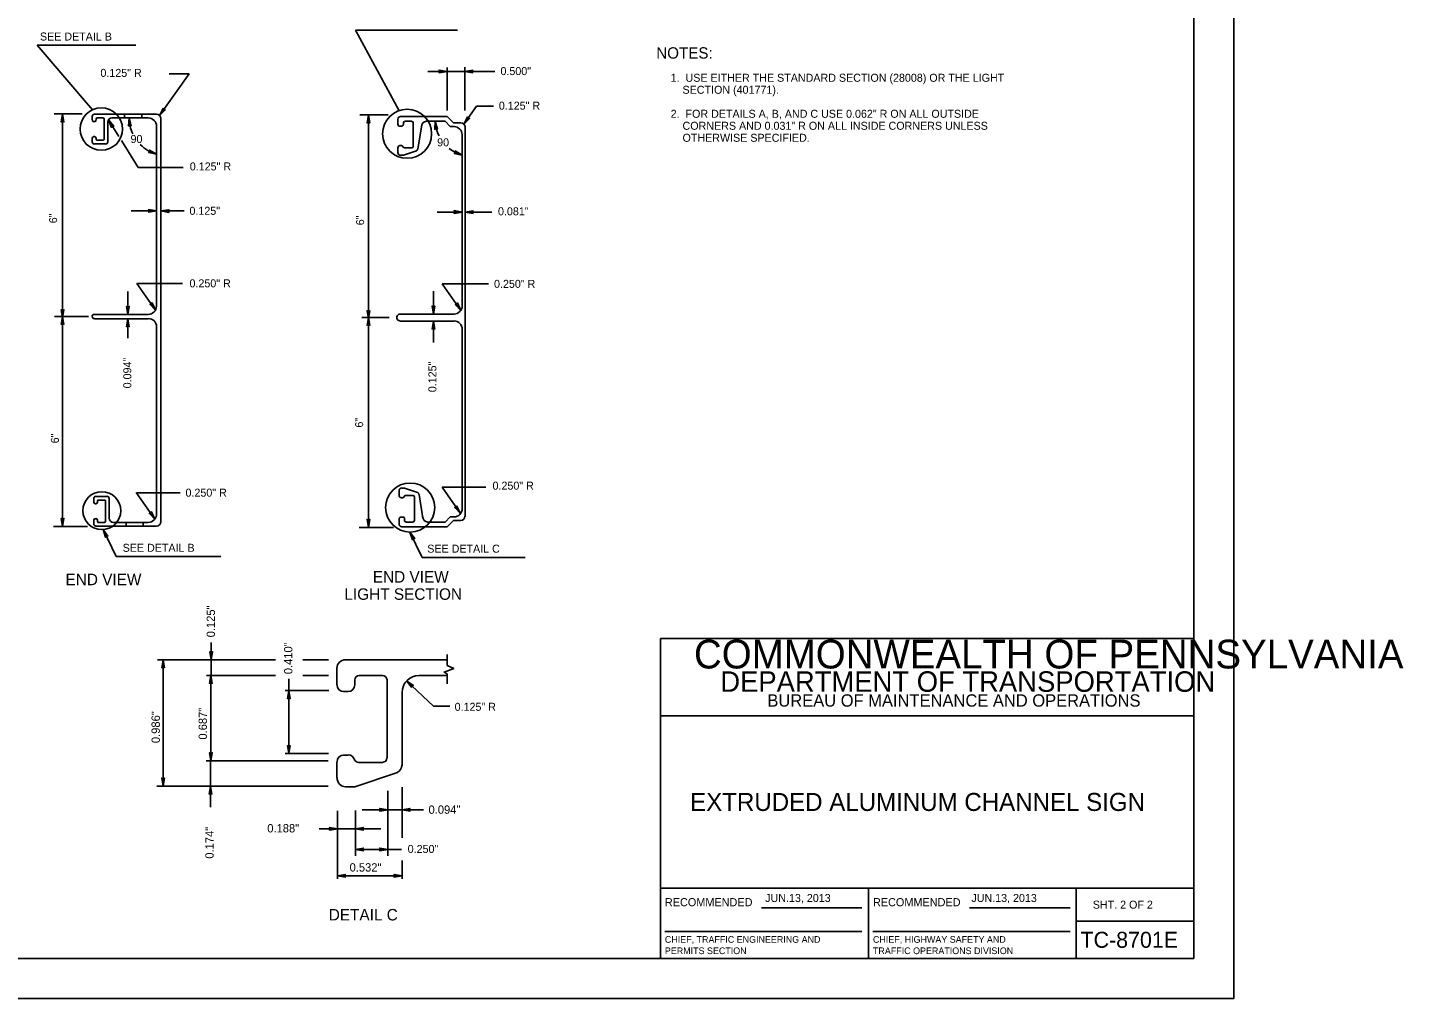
# Model space of a CAD drawing. Extents: x 647822 to 649292, y 298458 to 299646.
# Drawn here: x 648211 to 648727, y 298458 to 298822 of the extents above; entities that cross this region are included whole.
import ezdxf

# ---------------------------------------------------------------- set-up
doc = ezdxf.new("R2010")
doc.units = 0
for name, color, linetype in [('1', 7, 'Continuous'), ('2', 7, 'Continuous'), ('3', 7, 'Continuous'), ('XCS-GRID-MIN', 7, 'Continuous')]:
    doc.layers.add(name, color=color, linetype=linetype)

# ---------------------------------------------------------------- blocks, each defined once
blk = doc.blocks.new('RARROW')
at = {"layer": '3'}
blk.add_lwpolyline([(-2.2695, 0.285), (-2.184875, 0.12075), (0, 0), (-2.2695, 0.285), (-2.38575, 0.384625), (0, 0), (-2.183125, -0.108), (-2.262875, -0.2705), (0, 0), (-2.38575, -0.379125), (-2.262875, -0.2705)], dxfattribs=at)

msp = doc.modelspace()

# ---------------------------------------------------------------- linework, layer by layer
at = {"layer": '1'}
for p, q in [((648648.31, 298472.63), (648648.31, 299036.63)), ((648448.31, 298472.63), (648448.31, 298592.63)), ((648448.31, 298592.63), (648648.31, 298592.63)), ((648648.31, 298563.63), (648448.31, 298563.63)), ((648448.31, 298499), (648648.31, 298499)), ((648526.31, 298499), (648526.31, 298472.63)), ((648604.19, 298472.63), (648604.19, 298499)), ((648486.24, 298491.57), (648523.87, 298491.57)), ((648564.24, 298491.57), (648601.87, 298491.57)), ((648449.99, 298482.68), (648523.87, 298482.68)), ((648527.99, 298482.68), (648601.87, 298482.68)), ((648604.19, 298486.63), (648648.31, 298486.63)), ((648648.31, 298472.63), (647862.31, 298472.63)), ((647862.31, 298472.63), (648448.31, 298472.63))]:
    msp.add_line(p, q, dxfattribs=at)
at = {"layer": '2'}
for p, q in [((648372.22, 298820.73), (648333.97, 298820.73)), ((648350.25, 298790.63), (648333.97, 298820.73)), ((648214.75, 298815.06), (648235.45, 298790.86)), ((648251.69, 298815.06), (648214.75, 298815.06)), ((648260.57, 298788.63), (648271.68, 298804.33)), ((648271.68, 298804.33), (648264.19, 298804.33)), ((648375, 298805.22), (648361.12, 298805.22)), ((648368.38, 298790.5), (648368.38, 298806.72)), ((648375, 298790.5), (648375, 298806.85)), ((648386.25, 298805.22), (648375, 298805.22)), ((648374.65, 298785.41), (648379.38, 298792.13)), ((648385.69, 298792.13), (648379.38, 298792.13)), ((648231.57, 298789.25), (648221.07, 298789.25)), ((648224.19, 298712.88), (648224.19, 298789.25)), ((648235.32, 298787), (648235.32, 298788.38)), ((648236.19, 298786.38), (648235.94, 298786.38)), ((648236.19, 298789.13), (648259.44, 298789.13)), ((648236.82, 298787.38), (648236.82, 298787)), ((648239.32, 298787.75), (648237.19, 298787.75)), ((648239.82, 298779.75), (648239.82, 298787.38)), ((648241.44, 298787), (648245.32, 298780.77)), ((648256.32, 298787.75), (648242.69, 298787.75)), ((648247.44, 298789.13), (648247.44, 298787.75)), ((648253.94, 298787.75), (648253.94, 298789.13)), ((648261.07, 298787.5), (648261.07, 298636.38)), ((648346.25, 298788.88), (648335.62, 298788.88)), ((648338.88, 298712.5), (648338.88, 298788.88)), ((648349.88, 298787.25), (648349.88, 298785.38)), ((648368.38, 298788.25), (648350.88, 298788.25)), ((648355.12, 298786.5), (648352.5, 298786.5)), ((648363.38, 298786.5), (648360.5, 298786.5)), ((648360.62, 298786.5), (648367.62, 298786.5)), ((648369.5, 298784.5), (648367.62, 298786.5)), ((648370.75, 298785.88), (648368.38, 298788.25)), ((648241.19, 298786.13), (648241.19, 298778.75)), ((648259.44, 298717.25), (648259.44, 298784.63)), ((648351.25, 298784.63), (648350.62, 298784.63)), ((648352, 298786), (648352, 298785.38)), ((648355.62, 298777), (648355.62, 298786)), ((648357.38, 298776.13), (648358.88, 298785)), ((648371, 298784.5), (648369.5, 298784.5)), ((648373.53, 298785.88), (648370.75, 298785.88)), ((648374, 298717.38), (648374, 298781.5)), ((648375.12, 298638.38), (648375.12, 298784.28)), ((648235.32, 298778.75), (648235.32, 298780.13)), ((648235.94, 298780.75), (648236.19, 298780.75)), ((648240.32, 298778), (648236.19, 298778)), ((648236.82, 298780.13), (648236.82, 298779.75)), ((648237.19, 298779.38), (648239.32, 298779.38)), ((648246.32, 298779.25), (648252.57, 298769.25)), ((648349.88, 298776.63), (648349.88, 298774.75)), ((648350.62, 298777.38), (648351.25, 298777.38)), ((648352.38, 298776.5), (648355.12, 298776.5)), ((648350.88, 298773.75), (648352, 298773.75)), ((648352, 298773.75), (648356.88, 298775.38)), ((648269.36, 298769.25), (648252.57, 298769.25)), ((648259.44, 298752.88), (648249.94, 298752.88)), ((648269.81, 298752.88), (648261.07, 298752.88)), ((648374, 298752.5), (648364.62, 298752.5)), ((648385.13, 298752.5), (648375.12, 298752.5)), ((648259.07, 298715.75), (648252.07, 298725.75)), ((648269.14, 298725.75), (648252.07, 298725.75)), ((648373.5, 298715.63), (648366.5, 298725.63)), ((648383.82, 298725.63), (648366.5, 298725.63)), ((648248.69, 298714.13), (648248.69, 298722.75)), ((648363.25, 298714.25), (648363.25, 298722.88)), ((648236.19, 298714.13), (648256.32, 298714.13)), ((648371, 298714.25), (648350.88, 298714.25)), ((648233.94, 298713.38), (648221.19, 298713.38)), ((648224.19, 298634.63), (648224.19, 298713.38)), ((648256.32, 298712.5), (648236.19, 298712.5)), ((648248.69, 298705.14), (648248.69, 298712.5)), ((648259.44, 298639.25), (648259.44, 298709.5)), ((648346.64, 298713), (648336.38, 298713)), ((648338.88, 298634.25), (648338.88, 298713)), ((648371, 298711.63), (648350.75, 298711.63)), ((648363.25, 298703.55), (648363.25, 298711.63)), ((648374, 298641.13), (648374, 298708.5)), ((648258.82, 298637.38), (648251.82, 298647.38)), ((648268.24, 298647.25), (648252.07, 298647.25)), ((648350.38, 298646.25), (648350.38, 298648)), ((648351.38, 298649), (648352.38, 298649)), ((648352.38, 298649), (648357.25, 298647.38)), ((648373.38, 298639.5), (648366.5, 298649.38)), ((648382.89, 298649.38), (648366.5, 298649.38)), ((648235.94, 298643.75), (648235.94, 298645.13)), ((648236.69, 298643.13), (648236.44, 298643.13)), ((648236.69, 298645.88), (648240.94, 298645.88)), ((648237.32, 298644.13), (648237.32, 298643.75)), ((648239.94, 298644.5), (648237.69, 298644.5)), ((648240.32, 298636.5), (648240.32, 298644.13)), ((648241.69, 298645.13), (648241.69, 298637.75)), ((648351.12, 298645.38), (648351.62, 298645.38)), ((648352.88, 298646.25), (648355.62, 298646.25)), ((648356.12, 298645.75), (648356.12, 298636.88)), ((648357.88, 298646.63), (648359.25, 298637.75)), ((648235.94, 298635.5), (648235.94, 298637)), ((648236.44, 298637.5), (648236.69, 298637.5)), ((648237.32, 298637), (648237.32, 298636.5)), ((648350.38, 298635.5), (648350.38, 298637.38)), ((648351.62, 298638.13), (648351.12, 298638.13)), ((648352.38, 298636.88), (648352.38, 298637.38)), ((648367.62, 298636.25), (648369.5, 298638.25)), ((648370.75, 298636.88), (648368.38, 298634.5)), ((648369.5, 298638.25), (648371, 298638.25)), ((648373.5, 298636.88), (648370.75, 298636.88)), ((648233.57, 298634.63), (648220.82, 298634.63)), ((648259.44, 298634.75), (648236.69, 298634.75)), ((648237.69, 298636.13), (648239.94, 298636.13)), ((648244.32, 298623.38), (648239.47, 298633.45)), ((648243.32, 298636.13), (648256.32, 298636.13)), ((648248.07, 298636.13), (648248.07, 298634.75)), ((648254.44, 298634.75), (648254.44, 298636.13)), ((648348.25, 298634.25), (648335.38, 298634.25)), ((648368.38, 298634.5), (648351.38, 298634.5)), ((648355.62, 298636.25), (648352.88, 298636.25)), ((648359, 298623), (648354.38, 298632.5)), ((648363.75, 298636.25), (648361, 298636.25)), ((648361.12, 298636.25), (648367.62, 298636.25)), ((648283.53, 298623.38), (648244.32, 298623.38)), ((648397.61, 298623), (648359, 298623)), ((648279.97, 298578.75), (648279.97, 298591.14)), ((648368.33, 298582.5), (648368.33, 298586.63)), ((648303.99, 298584.63), (648259.77, 298584.63)), ((648261.88, 298537.25), (648261.88, 298584.63)), ((648323.9, 298584.63), (648314.33, 298584.63)), ((648327.08, 298581.43), (648327.08, 298575.25)), ((648368.21, 298584.63), (648330.28, 298584.63)), ((648278.19, 298578.75), (648303.99, 298578.75)), ((648279.84, 298546.75), (648279.84, 298578.75)), ((648308.99, 298549.42), (648308.99, 298577.43)), ((648314.33, 298578.75), (648323.9, 298578.75)), ((648333.78, 298577.03), (648333.78, 298575.28)), ((648335.34, 298578.75), (648344.13, 298578.75)), ((648345.83, 298547.75), (648345.83, 298577.05)), ((648353.18, 298576.72), (648363.25, 298567.17)), ((648368.33, 298578.75), (648357.86, 298578.75)), ((648368.33, 298575.63), (648368.33, 298579.38)), ((648323.97, 298573.05), (648307.69, 298573.05)), ((648331.31, 298572.67), (648329.56, 298572.67)), ((648351.46, 298544.88), (648351.46, 298572.35)), ((648369.42, 298567.17), (648363.25, 298567.17)), ((648323.9, 298549.42), (648307.62, 298549.42)), ((648323.74, 298546.75), (648278.08, 298546.75)), ((648279.72, 298529.31), (648279.72, 298546.75)), ((648327.08, 298546.25), (648327.08, 298540.38)), ((648329.46, 298548.88), (648331.33, 298548.88)), ((648335.21, 298546.13), (648344.21, 298546.13)), ((648333.71, 298537), (648349.71, 298542.38)), ((648323.75, 298537.25), (648259.5, 298537.25)), ((648330.33, 298537), (648333.71, 298537)), ((648346.08, 298511.1), (648346.08, 298535.5)), ((648351.46, 298517.84), (648351.46, 298536.88)), ((648346.08, 298528.38), (648336.46, 298528.38)), ((648345.71, 298528.38), (648340.5, 298528.38)), ((648359.08, 298528.38), (648346.08, 298528.38)), ((648359.53, 298528.38), (648351.33, 298528.38)), ((648327.21, 298502.53), (648327.21, 298528.04)), ((648333.96, 298511.1), (648333.96, 298528.16)), ((648333.96, 298521.29), (648320.4, 298521.29)), ((648343.55, 298521.29), (648333.96, 298521.29)), ((648338.35, 298521.29), (648333.96, 298521.29)), ((648327.21, 298514.22), (648327.21, 298514.09)), ((648351.21, 298513.52), (648333.96, 298513.52)), ((648351.46, 298502.53), (648351.46, 298509.41)), ((648351.46, 298503.63), (648327.21, 298503.63))]:
    msp.add_line(p, q, dxfattribs=at)
msp.add_lwpolyline([(648368.33, 298579.38), (648367.21, 298580), (648370.83, 298581.38), (648368.33, 298582.5)], dxfattribs=at)
for centre, radius in [((648238.75, 298783.61), 7.97), ((648353.36, 298781.82), 9.19), ((648238.93, 298640.52), 7.09), ((648354.51, 298641.68), 9.19)]:
    msp.add_circle(centre, radius, dxfattribs=at)
for centre, radius, start, end in [((648236.15, 298788.35), 0.795, 90, 180), ((648235.97, 298786.96), 0.612, 180, 270), ((648236.15, 298786.96), 0.612, 270, 0), ((648237.16, 298787.35), 0.398, 90, 180), ((648239.35, 298787.35), 0.398, 0, 90), ((648242.74, 298786.16), 1.59, 90, 180), ((648263.38, 298787.81), 14.21, 180.1857, 204.9016), ((648256.35, 298784.69), 3.08, 0, 90), ((648259.42, 298787.55), 1.6, 0, 90), ((648375.21, 298786.75), 11.37, 181.2701, 209.9237), ((648371, 298781.5), 3, 0, 90), ((648373.53, 298784.28), 1.6, 0, 90), ((648235.97, 298780.17), 0.612, 90, 180), ((648236.15, 298778.78), 0.795, 180, 270), ((648236.15, 298780.17), 0.612, 0, 90), ((648237.16, 298779.78), 0.398, 180, 270), ((648239.35, 298779.78), 0.398, 270, 0), ((648240.35, 298778.78), 0.795, 270, 0), ((648263.38, 298787.81), 14.21, 225.0505, 253.8315), ((648378.03, 298787.43), 14.21, 231.2831, 253.5327), ((648236.08, 298713.35), 0.818, 78.8792, 275.6682), ((648256.32, 298717.2), 3.08, 270, 0), ((648350.82, 298712.94), 1.31, 91.6847, 272.8064), ((648370.95, 298717.33), 3.08, 270, 0), ((648256.35, 298709.46), 3.08, 0, 90), ((648370.97, 298708.56), 3.08, 0, 90), ((648236.69, 298645.12), 0.795, 90, 180), ((648236.5, 298643.73), 0.612, 180, 270), ((648236.69, 298643.73), 0.612, 270, 0), ((648237.7, 298644.12), 0.398, 90, 180), ((648239.89, 298644.12), 0.398, 0, 90), ((648240.88, 298645.12), 0.795, 0, 90), ((648236.5, 298636.94), 0.612, 90, 180), ((648236.69, 298636.94), 0.612, 0, 90), ((648243.27, 298637.74), 1.59, 180, 270), ((648256.35, 298639.23), 3.08, 270, 0), ((648370.97, 298641.28), 3.08, 270, 0), ((648373.45, 298638.41), 1.6, 270, 0), ((648236.69, 298635.55), 0.795, 180, 270), ((648237.7, 298636.54), 0.398, 180, 270), ((648239.89, 298636.54), 0.398, 270, 0), ((648259.42, 298636.36), 1.6, 270, 0), ((648330.28, 298581.43), 3.2, 90, 180), ((648344.13, 298577.05), 1.7, 0, 90), ((648357.86, 298572.35), 6.4, 90, 180)]:
    msp.add_arc(centre, radius, start, end, dxfattribs=at)
for centre, major_axis, start_param, end_param in [((648350.89, 298787.24), (0, -1.04), 3.141593, 4.712389), ((648352.44, 298785.95), (0, -0.518), 3.141593, 4.712389), ((648355.13, 298785.95), (0, 0.518), 4.712389, 6.283185), ((648360.67, 298784.44), (0, -2.07), 3.141593, 4.712389), ((648350.66, 298785.43), (0, -0.797), 4.712389, 6.283185), ((648351.2, 298785.44), (0, 0.797), 3.141593, 4.712389), ((648350.66, 298776.58), (0, 0.797), 0, 1.570796), ((648351.2, 298776.59), (0, 0.797), 5.030839, 6.283185), ((648352.37, 298777.06), (0, -0.518), 5.099486, 6.283185), ((648355.13, 298777.06), (0, 0.518), 3.141593, 4.712389), ((648356.37, 298776.3), (0, -1.04), 0.462932, 1.480604), ((648350.89, 298774.78), (0, -1.04), 4.712389, 6.283185), ((648351.35, 298648.01), (0, -1.04), 3.141593, 4.712389), ((648356.83, 298646.49), (0, 1.04), 4.802582, 5.820253), ((648351.12, 298646.2), (0, -0.797), 4.712389, 6.283185), ((648351.67, 298646.19), (0, -0.797), 0, 1.252346), ((648352.84, 298645.73), (0, 0.518), 0, 1.183699), ((648355.6, 298645.73), (0, 0.518), 4.712389, 6.283185), ((648351.12, 298637.35), (0, -0.797), 3.141593, 4.712389), ((648351.67, 298637.34), (0, 0.797), 4.712389, 6.283185), ((648352.91, 298636.83), (0, -0.518), 4.712389, 6.283185), ((648355.6, 298636.83), (0, -0.518), 0, 1.570796), ((648361.14, 298638.34), (0, -2.07), 4.712389, 6.283185), ((648351.35, 298635.54), (0, -1.04), 4.712389, 6.283185), ((648329.56, 298575.28), (0, -2.61), 4.712389, 6.283185), ((648331.31, 298575.28), (0, 2.61), 3.141593, 4.712389), ((648335.38, 298577.03), (0, -1.7), 3.141593, 4.712389), ((648329.56, 298546.3), (0, 2.61), 0, 1.570796), ((648331.33, 298546.33), (0, 2.61), 5.030839, 6.283185), ((648335.17, 298547.86), (0, -1.7), 5.099486, 6.283185), ((648344.2, 298547.86), (0, 1.7), 3.141593, 4.712389), ((648348.24, 298545.37), (0, -3.39), 0.462932, 1.480604), ((648330.3, 298540.39), (0, -3.39), 4.712389, 6.283185)]:
    msp.add_ellipse(centre, major_axis=major_axis, ratio=0.943396, start_param=start_param, end_param=end_param, dxfattribs=at)
at = {"layer": 'XCS-GRID-MIN'}
msp.add_lwpolyline([(647822.31, 299051.63), (648663.31, 299051.63), (648663.31, 298457.63), (647822.31, 298457.63)], close=True, dxfattribs=at)

# ---------------------------------------------------------------- block references
at = {"layer": '2', "xscale": 1.2574347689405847, "yscale": 1.3092961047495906}
for p in [(648368.38, 298805.22), (648259.44, 298752.88), (648374, 298752.5), (648346.08, 298528.38), (648327.21, 298521.29), (648346.08, 298513.52), (648351.46, 298503.63)]:
    msp.add_blockref('RARROW', p, dxfattribs=at)
at = {"layer": '2'}
for p, xscale, yscale, rotation in [((648375, 298805.22), 1.2574347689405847, 1.3092961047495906, 180), ((648224.19, 298789.25), 1.2574347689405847, 1.3092961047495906, 89.99999999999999), ((648241.44, 298787), 1.2574347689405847, 1.3092961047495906, 121.93643129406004), ((648249.17, 298787.76), 1.2574347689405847, 1.3092961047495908, 95.3085792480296), ((648260.57, 298788.63), 1.2574347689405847, 1.3092961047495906, -125.1874600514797), ((648338.88, 298788.88), 1.2574347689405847, 1.3092961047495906, 89.99999999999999), ((648363.84, 298786.5), 1.257434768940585, 1.3092961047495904, 97.46813373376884), ((648374.65, 298785.41), 1.257434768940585, 1.3092961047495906, -124.96513947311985), ((648259.42, 298774.16), 1.257434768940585, 1.3092961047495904, -21.314522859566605), ((648374, 298773.8), 1.2574347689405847, 1.3092961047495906, -21.75660693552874), ((648261.07, 298752.88), 1.2574347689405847, 1.3092961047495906, 180), ((648375.12, 298752.5), 1.2574347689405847, 1.3092961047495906, 180), ((648224.19, 298712.88), 1.2574347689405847, 1.3092961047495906, -90.00000000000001), ((648248.69, 298714.13), 1.2574347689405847, 1.3092961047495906, -90.00000000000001), ((648259.07, 298715.75), 1.2574347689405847, 1.3092961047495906, -55.4952507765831), ((648338.88, 298712.5), 1.2574347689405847, 1.3092961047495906, -90.00000000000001), ((648363.25, 298714.25), 1.2574347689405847, 1.3092961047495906, -90.00000000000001), ((648373.5, 298715.63), 1.2574347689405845, 1.3092961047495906, -55.40907217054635), ((648224.19, 298713.38), 1.2574347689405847, 1.3092961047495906, 89.99999999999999), ((648248.69, 298712.5), 1.2574347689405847, 1.3092961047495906, 89.99999999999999), ((648338.88, 298713), 1.2574347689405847, 1.3092961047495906, 89.99999999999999), ((648363.25, 298711.63), 1.2574347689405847, 1.3092961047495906, 89.99999999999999), ((648373.38, 298639.5), 1.2574347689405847, 1.3092961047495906, -54.62763997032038), ((648224.19, 298634.63), 1.2574347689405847, 1.3092961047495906, -90.00000000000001), ((648258.82, 298637.38), 1.2574347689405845, 1.3092961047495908, -54.53715823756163), ((648338.88, 298634.25), 1.2574347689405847, 1.3092961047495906, -90.00000000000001), ((648239.47, 298633.45), 1.2574347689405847, 1.3092961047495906, 116.22067749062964), ((648354.38, 298632.5), 1.2574347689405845, 1.3092961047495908, 117.67480303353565), ((648279.97, 298584.63), 1.2574347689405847, 1.3092961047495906, -90.00000000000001), ((648261.88, 298584.63), 1.2574347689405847, 1.3092961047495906, 89.99999999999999), ((648279.84, 298578.75), 1.2574347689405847, 1.3092961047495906, 89.99999999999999), ((648353.18, 298576.72), 1.2574347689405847, 1.3092961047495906, 136.94148309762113), ((648308.99, 298573.05), 1.2574347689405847, 1.3092961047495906, 89.99999999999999), ((648279.84, 298546.75), 1.2574347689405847, 1.3092961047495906, -90.00000000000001), ((648308.99, 298549.42), 1.2574347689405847, 1.3092961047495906, -90.00000000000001), ((648261.88, 298537.25), 1.2574347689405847, 1.3092961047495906, -90.00000000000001), ((648279.72, 298537.25), 1.2574347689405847, 1.3092961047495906, 89.99999999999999), ((648351.46, 298528.38), 1.2574347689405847, 1.3092961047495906, 180), ((648333.96, 298521.29), 1.2574347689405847, 1.3092961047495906, 180), ((648333.96, 298513.52), 1.2574347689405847, 1.3092961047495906, 180), ((648327.21, 298503.63), 1.2574347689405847, 1.3092961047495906, 180)]:
    msp.add_blockref('RARROW', p, dxfattribs=dict(at, xscale=xscale, yscale=yscale, rotation=rotation))

# ---------------------------------------------------------------- texts
at = {"layer": '1'}
for s, height, p in [('COMMONWEALTH OF PENNSYLVANIA', 10.7828, (648460.9, 298581.36)), ('DEPARTMENT OF TRANSPORTATION', 7.6837, (648470.76, 298572.61)), ('BUREAU OF MAINTENANCE AND OPERATIONS', 4.6253, (648488.41, 298567.04)), ('EXTRUDED ALUMINUM CHANNEL SIGN', 6.75, (648459.45, 298527.94)), ('RECOMMENDED', 3.048, (648449.99, 298492.2)), ('RECOMMENDED', 3.048, (648527.99, 298492.2)), ('SHT. 2 OF 2', 3, (648610.4, 298491.31)), ('TC-8701E', 6, (648605.79, 298476.63)), ('CHIEF, TRAFFIC ENGINEERING AND', 2.5, (648449.99, 298478.51)), ('PERMITS SECTION', 2.5, (648449.99, 298474.26)), ('TRAFFIC OPERATIONS DIVISION', 2.5, (648527.99, 298474.26)), ('CHIEF, HIGHWAY SAFETY AND', 2.5, (648527.99, 298478.51))]:
    msp.add_text(s, height=height, dxfattribs=at).set_placement(p)
at = {"layer": '2'}
for s, height, p in [('SEE DETAIL B', 3, (648215.73, 298816.8)), ('NOTES:', 4.25, (648446.76, 298810.02)), ('0.125" R', 3, (648238.4, 298803.16)), ('0.500"', 3, (648388.36, 298803.84)), ('1.  USE EITHER THE STANDARD SECTION (28008) OR THE LIGHT', 3, (648452.15, 298801.33)), ('    SECTION (401771).', 3, (648452.15, 298796.83)), ('0.125" R', 3, (648387.75, 298790.88)), ('2.  FOR DETAILS A, B, AND C USE 0.062" R ON ALL OUTSIDE', 3, (648452.15, 298787.83)), ('    CORNERS AND 0.031" R ON ALL INSIDE CORNERS UNLESS', 3, (648452.15, 298783.33)), ('90', 3, (648249.69, 298778.38)), ('    OTHERWISE SPECIFIED.', 3, (648452.15, 298778.83)), ('90', 3, (648364.62, 298777.13)), ('0.125" R', 3, (648271.9, 298768.09)), ('0.125"', 3, (648271.78, 298751.45)), ('0.081"', 3, (648387.44, 298751.26)), ('0.250" R', 3, (648271.79, 298724.26)), ('0.250" R', 3, (648385.95, 298724.07)), ('0.250" R', 3, (648270.3, 298645.78)), ('0.250" R', 3, (648385.39, 298648.4)), ('SEE DETAIL B', 3, (648246.73, 298625.1)), ('SEE DETAIL C', 3, (648360.92, 298624.77)), ('END VIEW', 4.3, (648225.32, 298612.58)), ('END VIEW', 4.3, (648340.51, 298613.55)), ('LIGHT SECTION', 4.3, (648329.86, 298607.1)), ('0.125" R', 3, (648371.18, 298565.49)), ('0.094"', 3.125, (648361.39, 298526.88)), ('0.188"', 3.125, (648300.95, 298519.89)), ('0.250"', 3, (648353.58, 298512.19)), ('0.532"', 3.125, (648331.8, 298505.21)), ('JUN.13, 2013', 3, (648487.6, 298493.81)), ('JUN.13, 2013', 3, (648564.89, 298493.81)), ('DETAIL C', 4.3, (648323.99, 298486.88))]:
    msp.add_text(s, height=height, dxfattribs=at).set_placement(p)
for s, height, p in [('6"', 3, (648222.15, 298748.28)), ('6"', 3, (648337.25, 298747.53)), ('0.094"', 3, (648249.98, 298686.39)), ('0.125"', 3, (648364.34, 298684.93)), ('6"', 3, (648336.88, 298671.67)), ('6"', 3, (648222.83, 298665.76)), ('0.125"', 3.125, (648281.34, 298593.04)), ('0.410"', 3.125, (648310.36, 298579.21)), ('0.986"', 3.125, (648260.68, 298553.37)), ('0.687"', 3.125, (648278.33, 298554.69)), ('0.174"', 3.125, (648280.84, 298510.05))]:
    msp.add_text(s, height=height, rotation=90, dxfattribs=at).set_placement(p)

doc.saveas('drawing.dxf')
